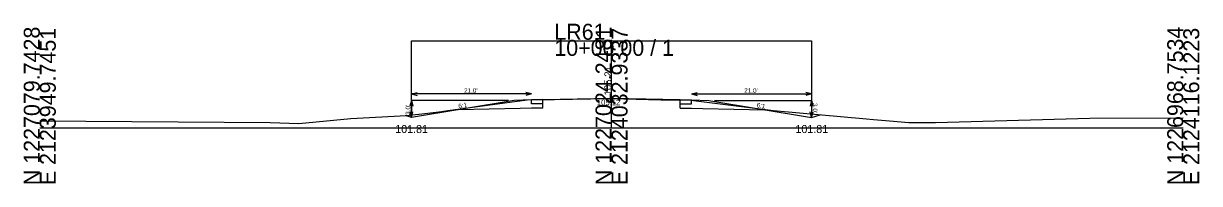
# Model space of a CAD drawing. Extents: x 2126751 to 2128979, y 1225108 to 1234639.
# Drawn here: x 2127773.8 to 2127979.4, y 1225107.5 to 1225135.4 of the extents above; entities that cross this region are included whole.
import ezdxf

# ---------------------------------------------------------------- set-up
doc = ezdxf.new("R2010")
doc.units = 0
for name, color, linetype in [('XS_CELL', 7, 'Continuous'), ('XS_M_DITCH', 7, 'Continuous'), ('XS_P_FINISHED_GRADE', 7, 'Continuous'), ('XS_P_FINISHED_GRADE_ELEV_TX', 7, 'Continuous'), ('XS_P_SUBGRADE_GRANULAR', 7, 'Continuous'), ('XS_P_SUBGRADE_LEVELING', 7, 'Continuous'), ('XS_P_SUBGRADE_PAVEMENT', 7, 'Continuous'), ('XS_P_TX_CLEARZONE', 7, 'Continuous'), ('XS_P_TX_DCH', 7, 'Continuous'), ('XS_P_TX_FS_BS', 7, 'Continuous'), ('XS_X_GROUND', 7, 'Continuous'), ('XS_X_GROUND_TX', 7, 'Continuous')]:
    doc.layers.add(name, color=color, linetype=linetype)

msp = doc.modelspace()

# ---------------------------------------------------------------- linework, layer by layer
at = {"layer": 'XS_CELL'}
for p, q in [((2127876.61, 1225117.21), (2127876.61, 1225132.6)), ((2127776.61, 1225117.21), (2127876.61, 1225117.21)), ((2127876.61, 1225117.21), (2127976.61, 1225117.21))]:
    msp.add_line(p, q, dxfattribs=at)
at = {"layer": 'XS_M_DITCH'}
for p, q in [((2127841.61, 1225119.02), (2127841.61, 1225132.42)), ((2127841.61, 1225132.42), (2127911.61, 1225132.42)), ((2127911.61, 1225132.42), (2127911.61, 1225119.02))]:
    msp.add_line(p, q, dxfattribs=at)
at = {"layer": 'XS_P_FINISHED_GRADE'}
for p, q in [((2127859.61, 1225122.02), (2127841.61, 1225119.02)), ((2127862.61, 1225122.14), (2127859.61, 1225122.02)), ((2127864.61, 1225122.18), (2127862.61, 1225122.14)), ((2127864.61, 1225122.18), (2127876.61, 1225122.42)), ((2127876.61, 1225122.42), (2127888.61, 1225122.18)), ((2127888.61, 1225122.18), (2127890.61, 1225122.14)), ((2127890.61, 1225122.14), (2127893.61, 1225122.02)), ((2127893.61, 1225122.02), (2127911.61, 1225119.02)), ((2127841.61, 1225119.02), (2127840.53, 1225119.38)), ((2127911.61, 1225119.02), (2127913.1, 1225119.52))]:
    msp.add_line(p, q, dxfattribs=at)
at = {"layer": 'XS_P_SUBGRADE_GRANULAR'}
for p, q in [((2127864.61, 1225120.68), (2127864.61, 1225121.43)), ((2127888.61, 1225120.68), (2127888.61, 1225121.43)), ((2127860.61, 1225120.6), (2127849.79, 1225120.39)), ((2127862.61, 1225120.64), (2127860.61, 1225120.6)), ((2127864.61, 1225120.68), (2127862.61, 1225120.64)), ((2127888.61, 1225120.68), (2127890.61, 1225120.64)), ((2127890.61, 1225120.64), (2127892.61, 1225120.6)), ((2127892.61, 1225120.6), (2127903.43, 1225120.39))]:
    msp.add_line(p, q, dxfattribs=at)
at = {"layer": 'XS_P_SUBGRADE_LEVELING'}
for p, q in [((2127864.61, 1225122.15), (2127866.66, 1225122.19)), ((2127864.61, 1225122.18), (2127864.61, 1225122.15)), ((2127866.66, 1225122.19), (2127876.13, 1225122.34)), ((2127876.13, 1225122.34), (2127876.61, 1225122.33)), ((2127876.61, 1225122.33), (2127885.24, 1225122.14)), ((2127885.24, 1225122.14), (2127888.61, 1225122.07)), ((2127888.61, 1225122.18), (2127888.61, 1225122.07))]:
    msp.add_line(p, q, dxfattribs=at)
at = {"layer": 'XS_P_SUBGRADE_PAVEMENT'}
for p, q in [((2127862.61, 1225121.39), (2127862.61, 1225122.14)), ((2127864.61, 1225121.43), (2127862.61, 1225121.39)), ((2127864.61, 1225121.43), (2127864.61, 1225122.15)), ((2127888.61, 1225121.43), (2127888.61, 1225122.07)), ((2127888.61, 1225121.43), (2127890.61, 1225121.39)), ((2127890.61, 1225121.39), (2127890.61, 1225122.14))]:
    msp.add_line(p, q, dxfattribs=at)
at = {"layer": 'XS_P_TX_CLEARZONE'}
for p, q in [((2127841.61, 1225123.14), (2127842.61, 1225123.39)), ((2127862.61, 1225123.14), (2127861.61, 1225123.39)), ((2127890.61, 1225123.14), (2127891.61, 1225123.39)), ((2127911.61, 1225123.14), (2127910.61, 1225123.39)), ((2127841.61, 1225122.02), (2127841.36, 1225121.02)), ((2127841.61, 1225123.14), (2127842.61, 1225122.89)), ((2127862.61, 1225123.14), (2127841.61, 1225123.14)), ((2127841.61, 1225122.02), (2127841.86, 1225121.02)), ((2127841.61, 1225122.02), (2127841.61, 1225119.02)), ((2127858.61, 1225122.02), (2127841.61, 1225122.02)), ((2127862.61, 1225123.14), (2127861.61, 1225122.89)), ((2127890.61, 1225123.14), (2127891.61, 1225122.89)), ((2127890.61, 1225123.14), (2127911.61, 1225123.14)), ((2127894.61, 1225122.02), (2127911.61, 1225122.02)), ((2127911.61, 1225123.14), (2127910.61, 1225122.89)), ((2127911.61, 1225122.02), (2127911.36, 1225121.02)), ((2127911.61, 1225122.02), (2127911.61, 1225119.02)), ((2127911.61, 1225122.02), (2127911.86, 1225121.02)), ((2127841.61, 1225119.02), (2127841.36, 1225120.02)), ((2127841.61, 1225119.02), (2127841.86, 1225120.02)), ((2127911.61, 1225119.02), (2127911.36, 1225120.02)), ((2127911.61, 1225119.02), (2127911.86, 1225120.02))]:
    msp.add_line(p, q, dxfattribs=at)
at = {"layer": 'XS_X_GROUND'}
for p, q in [((2127848, 1225120.23), (2127861.83, 1225122.11)), ((2127861.83, 1225122.11), (2127866.66, 1225122.19)), ((2127866.66, 1225122.19), (2127876.13, 1225122.34)), ((2127876.13, 1225122.34), (2127876.61, 1225122.33)), ((2127876.61, 1225122.33), (2127885.24, 1225122.14)), ((2127885.24, 1225122.14), (2127890.5, 1225122.03)), ((2127890.5, 1225122.03), (2127904.95, 1225120.25)), ((2127831.01, 1225118.85), (2127840.77, 1225119.4)), ((2127840.77, 1225119.4), (2127844.47, 1225119.81)), ((2127844.47, 1225119.81), (2127846.86, 1225120.07)), ((2127846.86, 1225120.07), (2127848, 1225120.23)), ((2127904.95, 1225120.25), (2127921.19, 1225118.8)), ((2127776.61, 1225118.43), (2127816.89, 1225118.16)), ((2127816.89, 1225118.16), (2127821.92, 1225117.98)), ((2127821.92, 1225117.98), (2127831.01, 1225118.85)), ((2127921.19, 1225118.8), (2127922.42, 1225118.67)), ((2127922.42, 1225118.67), (2127925.22, 1225118.47)), ((2127925.22, 1225118.47), (2127928.59, 1225118.17)), ((2127928.59, 1225118.17), (2127933.3, 1225118.16)), ((2127933.3, 1225118.16), (2127960.29, 1225118.9)), ((2127960.29, 1225118.9), (2127976.61, 1225118.97))]:
    msp.add_line(p, q, dxfattribs=at)

# ---------------------------------------------------------------- texts
at = {"layer": 'XS_CELL'}
for s, p in [('N 1227079.7428', (2127776.61, 1225107.21)), ('E 2123949.7451', (2127779.41, 1225107.21)), ('N 1227024.2481', (2127876.61, 1225107.21)), ('E 2124032.9337', (2127879.41, 1225107.21)), ('N 1226968.7534', (2127976.61, 1225107.21)), ('E 2124116.1223', (2127979.41, 1225107.21))]:
    msp.add_text(s, height=2.8, rotation=90, dxfattribs=at).set_placement(p)
for s, p in [('LR61', (2127866.61, 1225132.6)), ('10+00.00 / 1', (2127866.61, 1225129.8))]:
    msp.add_text(s, height=2.8, dxfattribs=at).set_placement(p)
at = {"layer": 'XS_P_FINISHED_GRADE_ELEV_TX'}
msp.add_text(' 105.21', height=1.25, rotation=90, dxfattribs=at).set_placement((2127876.61, 1225122.42))
at = {"layer": 'XS_P_TX_CLEARZONE'}
for p in [(2127850.82, 1225123.34), (2127899.82, 1225123.34)]:
    msp.add_text("21.0'", height=0.8, dxfattribs=at).set_placement(p)
for rotation, p in [(270, (2127911.81, 1225121.55)), (90, (2127841.41, 1225119.5))]:
    msp.add_text("3.0'", height=0.8, rotation=rotation, dxfattribs=at).set_placement(p)
at = {"layer": 'XS_P_TX_DCH'}
for p in [(2127838.78, 1225116.32), (2127908.78, 1225116.32)]:
    msp.add_text('101.81', height=1.4, dxfattribs=at).set_placement(p)
at = {"layer": 'XS_P_TX_FS_BS'}
for rotation, p in [(9.4623, (2127849.89, 1225120.61)), (350.5377, (2127901.95, 1225120.83))]:
    msp.add_text('6:1', height=0.8, rotation=rotation, dxfattribs=at).set_placement(p)
at = {"layer": 'XS_X_GROUND_TX'}
msp.add_text('105.12', height=1, dxfattribs=at).set_placement((2127874.05, 1225121.16))

doc.saveas('drawing.dxf')
